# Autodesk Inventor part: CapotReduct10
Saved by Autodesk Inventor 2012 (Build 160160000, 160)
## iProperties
Created: 2013-08
Part Number: CapotReduct10
Material: Default
Document SubType Name: Modeling
Designer: hilarion
Density: 1 g/cm^3
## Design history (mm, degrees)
node "CapotReduct101"
node "CapotReduct10"
node "Base1"
